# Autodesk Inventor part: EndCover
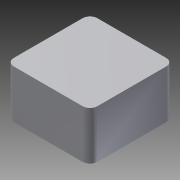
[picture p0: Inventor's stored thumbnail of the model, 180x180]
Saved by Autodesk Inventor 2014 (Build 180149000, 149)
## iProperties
Shininess: 64.0
Length Units: 11269
Angle Units: 11279
Time Units: 11290
Mass Units: 11283
Length Display Precision: 3
Angle Display Precision: 2
Compacted: True
Part Number: EndCover
Document SubType Name: Modeling
Created: 2002-12
Designer: dayb
Density: 1 g/cm^3
Mass: 54.8092 g
Surface Area: 94.0557 cm^2
Volume: 54.8092 cm^3
Material: Generic
Appearance: Default
Density: 0.0
Volumn: 0.0
Area: 0.0
PropertySet Name: Model Information
Control State: 0
Master: False
Checked Out: False
Author: dayb
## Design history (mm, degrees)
sketch "Sketch1"
  geometry: L1 (-19, 23)-(19, 23) reference; L2 (-23, -19)-(-23, 19) reference; L3 (19, -23)-(-19, -23) reference; L4 (23, 19)-(23, -19) reference; A1 r 4 centre (-19, 19) between (-19, 23) and (-23, 19) reference; A2 r 4 centre (-19, -19) between (-23, -19) and (-19, -23) reference; A3 r 4 centre (19, -19) between (19, -23) and (23, -19) reference; A4 r 4 centre (19, 19) between (23, 19) and (19, 23) reference; 1 further point
extrude "Extrusion1" new body sketch "Sketch1" distance "d0" = 26.5; taper "d1" = 0 deg
workplane "Work Plane2"
sketch "Sketch2"
  geometry: L1 (23, 0)-(23, 26.5) reference; L2 (19, 0)-(-19, 0) reference; L3 (23, 13)-(-0.334, 13); L4 (-0.334, 13)-(23, 13); L5 (23, 16.5)-(-0.334, 16.5); L6 (-0.334, 16.5)-(-0.334, 13)
  constraints: 8 end point, 2 parallel, 2 point on line, 1 collinear, 1 perpendicular
  dimensions: "d4" = 13 distance between parallel lines of L2 L3; "d5" = 7 diameter of L5 L3
revolve "Revolution1" sketch "Sketch2" stored, may be unused: angle "d6" = 90 deg
chamfer "Chamfer1" distance "d7" = 0.5; stored, may be unused: second distance "d8" = 2, angle "d11" = 45 deg
thread "Thread1" dims "d9" = 10, "d10" = 0
body "Solid1"
node "Reference1"
node "Reference2"
node "Reference3"
node "Reference4"
node "Reference5"
node "Reference6"
node "Reference7"
node "Reference8"
other parameters: "d2" = -6.5
